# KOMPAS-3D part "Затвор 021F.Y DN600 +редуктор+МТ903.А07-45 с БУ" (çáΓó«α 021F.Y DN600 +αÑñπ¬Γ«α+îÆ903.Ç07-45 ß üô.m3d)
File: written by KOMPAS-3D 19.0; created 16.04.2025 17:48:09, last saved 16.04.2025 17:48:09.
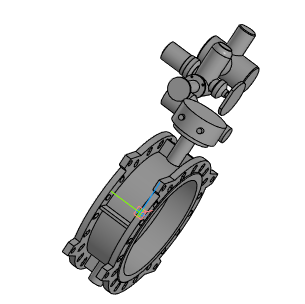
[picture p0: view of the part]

Document properties: Полное имя файла: Затвор 021F.Y DN600 +редуктор+МТ903.А07-45 с БУ.a3d

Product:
- Part/product: Затвор 021F.Y DN600 +редуктор+МТ903.А07-45 с БУ
    Масса: 471.076

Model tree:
1. Операция без истории:1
